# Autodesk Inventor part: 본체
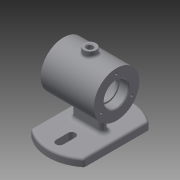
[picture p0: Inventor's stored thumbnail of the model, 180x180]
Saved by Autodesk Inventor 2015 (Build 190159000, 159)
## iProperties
Created: 2017-12
Part Number: 본체
Material: 일반
Document SubType Name: Modeling
Designer: 2-PC10
Density: 1 g/cm^3
Appearance: 기본값
Mass: 172.58 g
Surface Area: 486.484 cm^2
Volume: 172.58 cm^3
Author: 2-PC10
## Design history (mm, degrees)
sketch "스케치1"
  geometry: L1 (35, -42.426)-(35, 42.426); L2 (-35, 42.426)-(-35, -42.426); A1 r 55 centre (0, 0) between (-35, -42.426) and (35, -42.426); A2 r 55 centre (0, 0) between (35, 42.426) and (-35, 42.426); 4 further points
  constraints: 4 end point, 4 point on circle, 2 centre point, 2 horizontal alignment, 2 midpoint, 1 coincident, 1 parallel
  dimensions: "d1" = 70 distance between parallel lines of L1 L2; "d2" = 55 radius of A2; "d3" = 55 radius of A1; "d5" = 84.85281 distance of L1.start L1.end
extrude "돌출1" new body sketch "스케치1" distance "d6" = 10; taper "d7" = 0 deg
sketch "스케치2"
  geometry: L1 (-42.426, 0)-(42.426, 0) reference; C1 r 30 at (0, 62); 2 further points
  constraints: 1 centre point, 1 midpoint, 1 vertical alignment
  dimensions: "d8" = 60 diameter of C1; "d9" = 62 distance from line of L1 C1.centre
extrude "돌출2" join sketch "스케치2" stored distance "d10" = 70; taper "d11" = 0 deg
sketch "스케치3"
  geometry: L1 (-15, 5)-(15, 5); L2 (20, 0)-(20, 0); L3 (15, -5)-(-15, -5); L4 (-20, 0)-(-20, 0); L5 (-20, 5)-(20, -5); L6 (20, 5)-(-20, -5); A1 r 5 centre (-15, 0) between (-15, 5) and (-20, 0); A2 r 5 centre (-15, 0) between (-20, 0) and (-15, -5); A3 r 5 centre (15, 0) between (20, 0) and (15, 5); A4 r 5 centre (15, 0) between (15, -5) and (20, 0); 1 further point
  constraints: 12 end point, 8 point on circle, 8 point on line, 8 tangent, 4 centre point, 3 equal radius, 2 midpoint, 2 parallel, 1 horizontal, 1 perpendicular
  dimensions: "d12" = 10 distance between parallel lines of L3 L1; "d13" = 5 radius of A1; "d14" = 30 distance of A3.centre A1.centre
extrude "돌출3" join sketch "스케치3" stored distance "d15" = 70; taper "d16" = 0 deg
hole "구멍1" diameter "d19" = 28; stored, may be unused: countersink angle "d23" = 90 deg, drill point angle "d25" = 0 deg; dims "d17" = 10, "d18" = 10, "d20" = 6, "d21" = 4, "d22" = 2, "d24" = 8
hole "구멍2" diameter "d28" = 32; stored, may be unused: countersink angle "d32" = 90 deg, drill point angle "d34" = 0 deg; dims "d26" = 10, "d27" = 10, "d29" = 6, "d30" = 4, "d31" = 2, "d33" = 12
sketch "스케치4"
  geometry: C1 r 25 at (0, 62); C2 r 30 at (0, 62) reference; 1 further point
  constraints: 1 centre point, 1 concentric
  dimensions: "d35" = 50 diameter of C1
extrude "돌출4" cut sketch "스케치4" stored distance "d36" = 40; taper "d37" = 0 deg
node "작업 평면1"
sketch "스케치5"
  geometry: L1 (35, -30)-(35, 30) reference; C1 r 8 at (0, 0); 1 further point
  constraints: 1 centre point, 1 coincident
  dimensions: "d39" = 16 diameter of C1; "d40" = 35 distance from line of L1 C1.centre
extrude "돌출5" join sketch "스케치5" stored distance "d41" = 40; taper "d42" = 0 deg
hole "구멍3" diameter "d45" = 8; stored, may be unused: countersink angle "d49" = 90 deg, drill point angle "d51" = 0 deg; dims "d43" = 10, "d44" = 10, "d46" = 6, "d47" = 4, "d48" = 2, "d50" = 40
sketch "스케치6" dims "d52" = 46
  geometry: C1 r 30 at (0, 0) reference; 3 further points
  constraints: 2 horizontal alignment, 3 other
hole "구멍4" sketch "스케치6" at (-23, 0) diameter "d53" = 3.242; stored, may be unused: countersink angle "d57" = 90 deg, drill point angle "d59" = 118 deg; dims "d54" = 8, "d55" = 4, "d56" = 2, "d58" = 10
sketch "스케치7"
  geometry: L1 (0, -45)-(0, -19); L2 (5, -40)-(5, -24); L3 (-5, -24)-(-5, -40); L4 (0, 19)-(0, 45); L5 (5, 24)-(5, 40); L6 (-5, 40)-(-5, 24); A1 r 5 centre (0, -40) between (-5, -40) and (5, -40); A2 r 5 centre (0, -24) between (5, -24) and (-5, -24); A3 r 5 centre (0, 24) between (-5, 24) and (5, 24); A4 r 5 centre (0, 40) between (5, 40) and (-5, 40); 3 further points
  constraints: 16 end point, 12 point on circle, 8 tangent, 6 point on line, 4 centre point, 2 midpoint, 2 parallel, 1 vertical, 1 vertical alignment
  dimensions: "d63" = 10 distance between parallel lines of L3 L2; "d64" = 10 distance between parallel lines of L6 L5; "d65" = 16 distance of A2.centre A1.centre; "d66" = 16 distance of A4.centre A3.centre; "d67" = 24 distance of point (0, 0) A2.centre; "d68" = 24 distance of point (0, 0) A3.centre
extrude "돌출6" cut sketch "스케치7" stored distance "d69" = 40; taper "d70" = 0 deg
chamfer "모따기1" distance "d71" = 1; stored, may be unused: second distance "d72" = 2, angle "d73" = 45 deg
fillet "모깎기1" dims "d74" = 3
fillet "모깎기2" dims "d75" = 3
fillet "모깎기3" dims "d76" = 5
fillet "모깎기4" dims "d77" = 3
fillet "모깎기5" dims "d78" = 0.3
node "작업 평면2"
sketch "스케치8"
  geometry: L1 (-26, 5)-(26, 5); L2 (26, 5)-(26, -5); L3 (26, -5)-(-26, -5); L4 (-26, -5)-(-26, 5); L5 (-26, 0)-(26, 0); L6 (0, 5)-(0, -5); L7 (35, -30)-(35, 30) reference; L8 (-35, 30)-(-35, -30) reference; 1 further point
  constraints: 4 end point, 4 midpoint, 2 other
  dimensions: "d79" = 52 distance between parallel lines of L4 L2; "d80" = 10 distance between parallel lines of L3 L1; "d85" = 35 distance between parallel lines of L8 L6; "d86" = 30 distance from line of L8.start L5
feature "엠보싱1" sketch "스케치8" dims "d83" = 0.5, "d84" = 0
sketch "스케치9"
  geometry: 1 further point
node "솔리드1"
mirror "대칭1"
pattern_circular "원형 패턴1" dims angle "d61" = 360 deg
mirror "대칭2"
other parameters: "d38" = 99
